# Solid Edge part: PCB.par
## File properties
Author: Phip
Template: Normal.par
Last saved by: Phip
Revision: 18
Application: Solid Edge
Teilflächenrmatvorlage: Model Default
Coef. of Thermal Exp: 0.0
Thermal Conductivity: 0.0
Specific Heat: 0.0
Modulus of Elasticity: 0.0
Poission's Ratio: 0.0
Yield Stress: 0.0
Ultimate Stress: 0.0
Elongation: 0.0
Genauigkeit: 0.990
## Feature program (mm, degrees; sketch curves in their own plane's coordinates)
sketch for "unnamed Protrusion 1" plane through (0, 0, 0) normal (0, 0, 1) x-axis (1, 0, 0)
  line (-20.75, -54.15) -> (20.75, -54.15)
  line (20.75, -54.15) -> (20.75, 54.15)
  line (20.75, 54.15) -> (-20.75, 54.15)
  line (-20.75, 54.15) -> (-20.75, -54.15)
  dimension (linear) = 20.75
  dimension (linear) = 20.75
extrude "unnamed Protrusion 1" add finite 1.15 along -normal
sketch for "unnamed Hole 1" plane through (0, 0, 0) normal (0, 0, 1) x-axis (1, 0, 0)
  hole centre (-18.75, -30.15) bore radius 1
hole "unnamed Hole 1" through
sketch for "unnamed Hole 2" plane through (0, 0, 0) normal (0, 0, 1) x-axis (1, 0, 0)
  hole centre (-13.95, -49.95) bore radius 1
hole "unnamed Hole 2" through
sketch for "unnamed Hole 3" plane through (0, 0, 0) normal (0, 0, 1) x-axis (1, 0, 0)
  hole centre (16.95, 47.85) bore radius 1
hole "unnamed Hole 3" through
sketch for "unnamed Hole 4" plane through (0, 0, 0) normal (0, 0, 1) x-axis (1, 0, 0)
  hole centre (18.75, -30.15) bore radius 1
hole "unnamed Hole 4" through
sketch for "unnamed Hole 5" plane through (0, 0, 0) normal (0, 0, 1) x-axis (1, 0, 0)
  hole centre (13.95, -49.95) bore radius 1
hole "unnamed Hole 5" through
sketch for "unnamed Hole 6" plane through (0, 0, 0) normal (0, 0, 1) x-axis (1, 0, 0)
  hole centre (-16.95, 47.85) bore radius 1
hole "unnamed Hole 6" through
holes "Schraubenlöcher" diameter 2: "unnamed Hole 1", "unnamed Hole 2", "unnamed Hole 3", "unnamed Hole 4", "unnamed Hole 5", "unnamed Hole 6"
sketch for "unnamed Cutout 1" #1 plane through (0, 0, 0) normal (0, 0, 1) x-axis (1, 0, 0)
  line (20.75, 54.15) -> (20.75, 40.15)
  line (20.75, 40.15) -> (18.55, 50.05)
  line (18.55, 50.05) -> (14.35, 50.05)
  line (14.35, 50.05) -> (14.35, 54.15)
  line (14.35, 54.15) -> (20.75, 54.15)
sketch for "unnamed Cutout 1" #2 plane through (0, 0, 0) normal (0, 0, 1) x-axis (1, 0, 0)
  line (10.75, 54.15) -> (10.75, 53.25)
  line (10.75, 53.25) -> (5.25, 53.25)
  line (5.25, 53.25) -> (5.25, 54.15)
  line (10.75, 54.15) -> (5.25, 54.15)
sketch for "unnamed Cutout 1" #3 plane through (0, 0, 0) normal (0, 0, 1) x-axis (1, 0, 0)
  line (-20.75, 54.15) -> (-20.75, 40.15)
  line (-20.75, 40.15) -> (-18.55, 50.05)
  line (-18.55, 50.05) -> (-14.35, 50.05)
  line (-14.35, 50.05) -> (-14.35, 54.15)
  line (-14.35, 54.15) -> (-20.75, 54.15)
  dimension (linear) = 18.55
extrude "unnamed Cutout 1" cut through along -normal
sketch for "unnamed Cutout 2" #1 plane through (0, 0, 0) normal (0, 0, 1) x-axis (1, 0, 0)
  line (20.75, -28.15) -> (20.75, -54.15)
  line (20.75, -54.15) -> (16.0259, -54.15)
  line (17.75, -44.15) -> (16.0259, -54.15)
  line (18.75, -44.15) -> (17.75, -44.15)
  line (20.75, -28.15) -> (18.75, -44.15)
sketch for "unnamed Cutout 2" #2 plane through (0, 0, 0) normal (0, 0, 1) x-axis (1, 0, 0)
  line (-20.75, -28.15) -> (-20.75, -54.15)
  line (-20.75, -54.15) -> (-16.0259, -54.15)
  line (-17.75, -44.15) -> (-16.0259, -54.15)
  line (-18.75, -44.15) -> (-17.75, -44.15)
  line (-20.75, -28.15) -> (-18.75, -44.15)
extrude "unnamed Cutout 2" cut through along -normal
fillet "Verrundung_1" radius 4
fillet "Verrundung_2" radius 1
sketch for "unnamed Hole 7" plane through (0, 0, -1.15) normal (0, 0, -1) x-axis (-1, 0, 0)
  hole centre (17.4, -36.95) bore radius 0.85
hole "unnamed Hole 7" through
sketch for "unnamed Hole 8" plane through (0, 0, -1.15) normal (0, 0, -1) x-axis (-1, 0, 0)
  hole centre (12.05, 51.75) bore radius 0.85
hole "unnamed Hole 8" through
holes "Positionierungen_klein" diameter 1.7: "unnamed Hole 7", "unnamed Hole 8"
sketch for "unnamed Cutout 3" plane through (0, 0, -1.15) normal (0, 0, -1) x-axis (-1, 0, 0)
  line (1.1, -49.6) -> (1.1, -52.2)
  line (3.2, -49.6) -> (3.2, -52.2)
extrude "unnamed Cutout 3" cut through along -normal
sketch for "unnamed Hole 9" plane through (0, 0, -1.15) normal (0, 0, -1) x-axis (-1, 0, 0)
  hole centre (-4.15, -1.15) bore radius 1.1
hole "unnamed Hole 9" through
sketch for "unnamed Hole 10" plane through (0, 0, -1.15) normal (0, 0, -1) x-axis (-1, 0, 0)
  hole centre (-7.75, -28.15) bore radius 1.1
hole "unnamed Hole 10" through
sketch for "unnamed Hole 11" plane through (0, 0, -1.15) normal (0, 0, -1) x-axis (-1, 0, 0)
  hole centre (-7.75, -41.15) bore radius 1.1
hole "unnamed Hole 11" through
sketch for "unnamed Hole 12" plane through (0, 0, -1.15) normal (0, 0, -1) x-axis (-1, 0, 0)
  hole centre (15.45, -1.15) bore radius 1.1
hole "unnamed Hole 12" through
sketch for "unnamed Hole 13" plane through (0, 0, -1.15) normal (0, 0, -1) x-axis (-1, 0, 0)
  hole centre (4.15, -1.15) bore radius 1.1
hole "unnamed Hole 13" through
sketch for "unnamed Hole 14" plane through (0, 0, -1.15) normal (0, 0, -1) x-axis (-1, 0, 0)
  hole centre (7.75, -28.15) bore radius 1.1
hole "unnamed Hole 14" through
sketch for "unnamed Hole 15" plane through (0, 0, -1.15) normal (0, 0, -1) x-axis (-1, 0, 0)
  hole centre (7.75, -41.15) bore radius 1.1
hole "unnamed Hole 15" through
sketch for "unnamed Hole 16" plane through (0, 0, -1.15) normal (0, 0, -1) x-axis (-1, 0, 0)
  hole centre (-15.45, -1.15) bore radius 1.1
hole "unnamed Hole 16" through
holes "LEDs" diameter 2.2: "unnamed Hole 9", "unnamed Hole 10", "unnamed Hole 11", "unnamed Hole 12", "unnamed Hole 13", "unnamed Hole 14", "unnamed Hole 15", "unnamed Hole 16"
sketch for "Tastenfeld" #1 plane through (0, 0, -1.15) normal (0, 0, -1) x-axis (-1, 0, 0)
  circle centre (0, -45.65) radius 3.15
sketch for "Tastenfeld" #2 plane through (0, 0, -1.15) normal (0, 0, -1) x-axis (-1, 0, 0)
  circle centre (12.75, -44.15) radius 3.15
sketch for "Tastenfeld" #3 plane through (0, 0, -1.15) normal (0, 0, -1) x-axis (-1, 0, 0)
  circle centre (-13, -35.65) radius 3.15
sketch for "Tastenfeld" #4 plane through (0, 0, -1.15) normal (0, 0, -1) x-axis (-1, 0, 0)
  circle centre (0, -37.65) radius 3.15
sketch for "Tastenfeld" #5 plane through (0, 0, -1.15) normal (0, 0, -1) x-axis (-1, 0, 0)
  circle centre (13, -35.65) radius 3.15
sketch for "Tastenfeld" #6 plane through (0, 0, -1.15) normal (0, 0, -1) x-axis (-1, 0, 0)
  circle centre (-13, -28.15) radius 3.15
sketch for "Tastenfeld" #7 plane through (0, 0, -1.15) normal (0, 0, -1) x-axis (-1, 0, 0)
  circle centre (0, -29.65) radius 3.15
sketch for "Tastenfeld" #8 plane through (0, 0, -1.15) normal (0, 0, -1) x-axis (-1, 0, 0)
  circle centre (13, -28.15) radius 3.15
sketch for "Tastenfeld" #9 plane through (0, 0, -1.15) normal (0, 0, -1) x-axis (-1, 0, 0)
  circle centre (-16.1605, -20.15) radius 3.15
sketch for "Tastenfeld" #10 plane through (0, 0, -1.15) normal (0, 0, -1) x-axis (-1, 0, 0)
  circle centre (0, -21.65) radius 3.15
sketch for "Tastenfeld" #11 plane through (0, 0, -1.15) normal (0, 0, -1) x-axis (-1, 0, 0)
  circle centre (16.1605, -19.15) radius 3.15
sketch for "Tastenfeld" #12 plane through (0, 0, -1.15) normal (0, 0, -1) x-axis (-1, 0, 0)
  circle centre (-12.5, -8.65) radius 3.15
sketch for "Tastenfeld" #13 plane through (0, 0, -1.15) normal (0, 0, -1) x-axis (-1, 0, 0)
  circle centre (0, -4.65) radius 3.15
sketch for "Tastenfeld" #14 plane through (0, 0, -1.15) normal (0, 0, -1) x-axis (-1, 0, 0)
  circle centre (7, -12.15) radius 3.15
sketch for "Tastenfeld" #15 plane through (0, 0, -1.15) normal (0, 0, -1) x-axis (-1, 0, 0)
  circle centre (14, -7.15) radius 3.15
sketch for "Tastenfeld" #16 plane through (0, 0, -1.15) normal (0, 0, -1) x-axis (-1, 0, 0)
  circle centre (-12.75, -44.15) radius 3.15
extrude "Tastenfeld" cut finite 0.1 along -normal
sketch for "Lautsprecher" #1 plane through (0, 0, -1.15) normal (0, 0, -1) x-axis (-1, 0, 0)
  circle centre (0, 45.65) radius 2.95
sketch for "Lautsprecher" #2 plane through (0, 0, -1.15) normal (0, 0, -1) x-axis (-1, 0, 0)
  circle centre (0, 45.65) radius 1.15
extrude "Lautsprecher" cut finite 0.1 along -normal
sketch for "Display" plane through (0, 0, -1.15) normal (0, 0, -1) x-axis (-1, 0, 0)
  line (-4.475, 33.15) -> (-3.575, 33.15)
  line (-3.575, 33.15) -> (-3.575, 36.15)
  line (-3.575, 36.15) -> (-4.475, 36.15)
  line (-4.475, 36.15) -> (-4.475, 33.15)
  dimension (linear) = 4.475
  dimension (linear) = 3.575
extrude "Display" cut finite 0.1 along -normal
pattern "unnamed Pattern 1" of "Display"
extrude "unnamed Cutout 4" cut finite 0.1
extrude "unnamed Cutout 5" cut finite 0.1
extrude "unnamed Cutout 6" cut finite 0.1
extrude "unnamed Cutout 7" cut finite 0.1
extrude "unnamed Cutout 8" cut finite 0.1
extrude "unnamed Cutout 9" cut finite 0.1
extrude "unnamed Cutout 10" cut finite 0.1
sketch for "Display_Positionierung" plane through (0, 0, -1.15) normal (0, 0, -1) x-axis (-1, 0, 0)
  hole centre (6.05, 32.15) bore radius 1
hole "Display_Positionierung" diameter 2 through
sketch for "Schalter" plane through (0, 0, 0) normal (0, 0, 1) x-axis (1, 0, 0)
  line (-15.05, 32.85) -> (18.75, 32.85)
  line (18.75, 32.85) -> (18.75, 41.85)
  line (18.75, 41.85) -> (11.75, 48.85)
  line (11.75, 48.85) -> (-12.05, 48.85)
  line (-12.05, 48.85) -> (-15.05, 45.85)
  line (-15.05, 45.85) -> (-15.05, 32.85)
extrude "Schalter" add finite 1.7 along +normal
sketch for "Abschirmung_3" plane through (0, 0, 0) normal (0, 0, 1) x-axis (1, 0, 0)
extrude "Abschirmung_3" add finite 2.7 along +normal
sketch for "unnamed Protrusion 2" plane through (0, 0, 0) normal (0, 0, 1) x-axis (1, 0, 0)
extrude "unnamed Protrusion 2" add along +normal
sketch for "unnamed Protrusion 3" #1 plane through (0, 0, 0) normal (0, 0, 1) x-axis (1, 0, 0)
  line (-15.55, -6.3744) -> (-12.85, -7.9333)
  arc centre (-13.6, -9.2323) radius 1.5 from (-12.85, -7.9333) to (-12.1, -9.2323) cw
  line (-12.1, -9.2323) -> (-12.1, -12.35)
  arc centre (-13.6, -12.35) radius 1.5 from (-12.1, -12.35) to (-14.35, -13.649) cw
  line (-14.35, -13.649) -> (-17.05, -12.0902)
  arc centre (-16.3, -10.7912) radius 1.5 from (-17.05, -12.0902) to (-17.8, -10.7912) cw
  line (-17.8, -10.7912) -> (-17.8, -7.6735)
  arc centre (-16.3, -7.6735) radius 1.5 from (-15.55, -6.3744) to (-17.8, -7.6735) ccw
sketch for "unnamed Protrusion 3" #2 plane through (0, 0, 0) normal (0, 0, 1) x-axis (1, 0, 0)
  line (5, -10.25) -> (5, -12.75)
  line (8, -12.75) -> (8, -10.25)
sketch for "unnamed Protrusion 3" #3 plane through (0, 0, 0) normal (0, 0, 1) x-axis (1, 0, 0)
extrude "unnamed Protrusion 3" add along +normal
sketch for "Kondensator" plane through (0, 0, 0) normal (0, 0, 1) x-axis (1, 0, 0)
extrude "Kondensator" add finite 2.75 along +normal
sketch for "Antenne" #1 plane through (0, 0, 0) normal (0, 0, 1) x-axis (1, 0, 0)
sketch for "Antenne" #2 plane through (0, 0, 0) normal (0, 0, 1) x-axis (1, 0, 0)
extrude "Antenne" cut finite 0.1 along -normal
sketch for "Akku" #1 plane through (0, 0, 0) normal (0, 0, 1) x-axis (1, 0, 0)
sketch for "Akku" #2 plane through (0, 0, 0) normal (0, 0, 1) x-axis (1, 0, 0)
  line (-0.15, 29.05) -> (2.45, 29.05)
  line (2.45, 29.05) -> (2.45, 31.65)
  line (2.45, 31.65) -> (-0.15, 31.65)
  line (-0.15, 31.65) -> (-0.15, 29.05)
sketch for "Akku" #3 plane through (0, 0, 0) normal (0, 0, 1) x-axis (1, 0, 0)
  line (3.55, 29.05) -> (6.15, 29.05)
  line (6.15, 29.05) -> (6.15, 31.65)
  line (6.15, 31.65) -> (3.55, 31.65)
  line (3.55, 31.65) -> (3.55, 29.05)
sketch for "Akku" #4 plane through (0, 0, 0) normal (0, 0, 1) x-axis (1, 0, 0)
extrude "Akku" cut finite 0.1 along -normal
sketch for "Vibrator" #1 plane through (0, 0, 0) normal (0, 0, 1) x-axis (1, 0, 0)
sketch for "Vibrator" #2 plane through (0, 0, 0) normal (0, 0, 1) x-axis (1, 0, 0)
extrude "Vibrator" cut finite 0.1 along -normal
sketch for "SIM" plane through (0, 0, 0) normal (0, 0, 1) x-axis (1, 0, 0)
extrude "SIM" cut finite 0.1 along -normal
pattern "unnamed Pattern 2" of "SIM"
extrude "unnamed Cutout 11" cut finite 0.1
extrude "unnamed Cutout 12" cut finite 0.1
extrude "unnamed Cutout 13" cut finite 0.1
extrude "unnamed Cutout 14" cut finite 0.1
extrude "unnamed Cutout 15" cut finite 0.1
sketch for "Pieper" #1 plane through (0, 0, 0) normal (0, 0, 1) x-axis (1, 0, 0)
  line (14.15, -42.75) -> (16.65, -42.75)
  line (16.65, -42.75) -> (16.65, -39.35)
  line (16.65, -39.35) -> (14.15, -39.35)
  line (14.15, -39.35) -> (14.15, -42.75)
sketch for "Pieper" #2 plane through (0, 0, 0) normal (0, 0, 1) x-axis (1, 0, 0)
  line (15.15, -36.25) -> (17.65, -36.25)
  line (17.65, -36.25) -> (17.65, -32.85)
  line (17.65, -32.85) -> (15.15, -32.85)
  line (15.15, -32.85) -> (15.15, -36.25)
  dimension (linear) = 17.65
  dimension (linear) = 17.65
  dimension (linear) = 17.65
extrude "Pieper" cut finite 0.1 along -normal
sketch for "Mikrofon" #1 plane through (0, 0, 0) normal (0, 0, 1) x-axis (1, 0, 0)
  line (-10.9, -53.45) -> (-6.1, -53.45)
  line (-6.1, -53.45) -> (-6.1, -50.45)
  line (-6.1, -50.45) -> (-10.9, -50.45)
  line (-10.9, -50.45) -> (-10.9, -53.45)
sketch for "Mikrofon" #2 plane through (0, 0, 0) normal (0, 0, 1) x-axis (1, 0, 0)
  line (-10.9, -50.25) -> (-6.1, -50.25)
  line (-6.1, -50.25) -> (-6.1, -47.25)
  line (-6.1, -47.25) -> (-10.9, -47.25)
  line (-10.9, -47.25) -> (-10.9, -50.25)
  dimension (linear) = 10.9
extrude "Mikrofon" cut finite 0.1 along -normal
sketch for "Klinke_2" #1 plane through (0, 0, 0) normal (0, 0, 1) x-axis (1, 0, 0)
  line (-5.9, -51.05) -> (-3.9, -51.05)
  line (-3.9, -51.05) -> (-3.9, -48.15)
  line (-3.9, -48.15) -> (-5.9, -48.15)
  line (-5.9, -48.15) -> (-5.9, -51.05)
sketch for "Klinke_2" #2 plane through (0, 0, 0) normal (0, 0, 1) x-axis (1, 0, 0)
  line (-0.4, -45.55) -> (1.5, -45.55)
  line (1.5, -45.55) -> (1.5, -43.05)
  line (1.5, -43.05) -> (-0.4, -43.05)
  line (-0.4, -43.05) -> (-0.4, -45.55)
sketch for "Klinke_2" #3 plane through (0, 0, 0) normal (0, 0, 1) x-axis (1, 0, 0)
  line (2.4, -45.55) -> (4.3, -45.55)
  line (4.3, -45.55) -> (4.3, -43.05)
  line (4.3, -43.05) -> (2.4, -43.05)
  line (2.4, -43.05) -> (2.4, -45.55)
sketch for "Klinke_2" #4 plane through (0, 0, 0) normal (0, 0, 1) x-axis (1, 0, 0)
  line (1, -48.45) -> (2.9, -48.45)
  line (2.9, -48.45) -> (2.9, -46.15)
  line (2.9, -46.15) -> (1, -46.15)
  line (1, -46.15) -> (1, -48.45)
sketch for "Klinke_2" #5 plane through (0, 0, 0) normal (0, 0, 1) x-axis (1, 0, 0)
  line (-5.9, -46.05) -> (-3.9, -46.05)
  line (-3.9, -46.05) -> (-3.9, -43.15)
  line (-3.9, -43.15) -> (-5.9, -43.15)
  line (-5.9, -43.15) -> (-5.9, -46.05)
  dimension (linear) = 5.9
  dimension (linear) = 3.9
  dimension (linear) = 2.9
extrude "Klinke_2" cut finite 0.1 along -normal
sketch for "Netzteil" #1 plane through (0, 0, 0) normal (0, 0, 1) x-axis (0, 1, 0)
  line (-52.85, -7) -> (-49.75, -7)
  line (-49.75, -7) -> (-49.75, -9)
  line (-49.75, -9) -> (-52.85, -9)
  line (-52.85, -9) -> (-52.85, -7)
sketch for "Netzteil" #2 plane through (0, 0, 0) normal (0, 0, 1) x-axis (0, 1, 0)
  line (-45.45, -8.5) -> (-42.85, -8.5)
  line (-42.85, -8.5) -> (-42.85, -10.5)
  line (-42.85, -10.5) -> (-45.45, -10.5)
  line (-45.45, -10.5) -> (-45.45, -8.5)
sketch for "Netzteil" #3 plane through (0, 0, 0) normal (0, 0, 1) x-axis (0, 1, 0)
  line (-47.35, -4.9) -> (-43.65, -4.9)
  line (-43.65, -4.9) -> (-43.65, -6.9)
  line (-43.65, -6.9) -> (-47.35, -6.9)
  line (-47.35, -6.9) -> (-47.35, -4.9)
  dimension (linear) = 43.65
  dimension (linear) = 47.35
  dimension (linear) = 47.35
extrude "Netzteil" cut finite 0.1 along -normal
sketch for "Testpunkte" #1 plane through (0, 0, 0) normal (0, 0, 1) x-axis (1, 0, 0)
  circle centre (-16.3, -10.7912) radius 1
sketch for "Testpunkte" #2 plane through (0, 0, 0) normal (0, 0, 1) x-axis (1, 0, 0)
  circle centre (-13.6, -12.35) radius 1
sketch for "Testpunkte" #3 plane through (0, 0, 0) normal (0, 0, 1) x-axis (1, 0, 0)
  circle centre (-13.6, -9.2323) radius 1
sketch for "Testpunkte" #4 plane through (0, 0, 0) normal (0, 0, 1) x-axis (1, 0, 0)
  circle centre (6.5, -12.75) radius 1
sketch for "Testpunkte" #5 plane through (0, 0, 0) normal (0, 0, 1) x-axis (1, 0, 0)
  circle centre (6.5, -10.25) radius 1
sketch for "Testpunkte" #6 plane through (0, 0, 0) normal (0, 0, 1) x-axis (1, 0, 0)
  circle centre (-16.3, -7.6735) radius 1
extrude "Testpunkte" cut finite 0.1 along -normal
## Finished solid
Body 1: solid body, 318 faces, 701 edges, 410 vertices.
  Faces by surface: plane 259, cylinder 59
  Edges by curve: line 580, circle 121
Bounding box of the edges (mm): 41.500 x 108.300 x 3.900, from (-20.75, -54.15, -1.15) to (20.75, 54.15, 2.75).
Cylindrical faces by radius (mm): R0.85 x2, R0.9 x2, R1 x19, R1.05 x2, R1.1 x8, R1.15 x1, R1.5 x6, R2.95 x1, R3.15 x16, R4 x2
Planar faces by outward normal: +x 44, +y 44, +z 40, -x 44, -y 40, -z 35, oblique 12
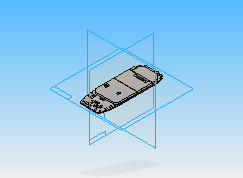
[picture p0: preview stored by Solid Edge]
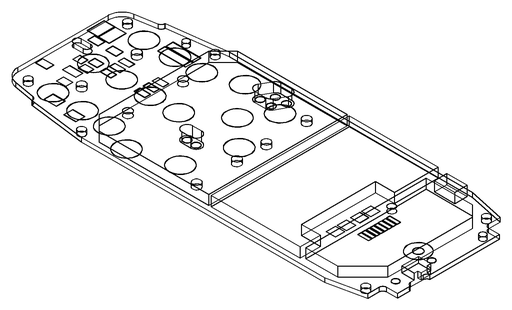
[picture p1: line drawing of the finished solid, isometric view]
